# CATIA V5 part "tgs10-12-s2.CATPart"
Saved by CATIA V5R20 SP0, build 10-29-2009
Part number: TGS10-12-S2
Revision: 1
Definition: design
Nomenclature: TGS10-12-S2
Source: made
Description: NOT SPECIFIED
Bounding box of the stored display mesh (mm): x -22 to 0.8, y 0 to 10, z -4 to 4
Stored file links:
  C:\Users\Raffaele\Desktop\3D X SITO CF\I-MOLD\TGS-S2\tgs10-s2.step\tgs10-12-s2.CATPart
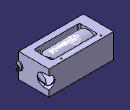
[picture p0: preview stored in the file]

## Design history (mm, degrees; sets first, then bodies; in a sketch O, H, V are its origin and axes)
Set1
  Line1 "LINE #4248": stored without definition
  DatumCurve1 "COMPOSITE_CURVE #4319"
  DatumCurve2 "COMPOSITE_CURVE #4370"
  DatumCurve3 "COMPOSITE_CURVE #4449"
  DatumCurve4 "COMPOSITE_CURVE #4492"
  DatumCurve5 "COMPOSITE_CURVE #4721"
  DatumCurve6 "COMPOSITE_CURVE #4863"
  DatumCurve7 "COMPOSITE_CURVE #4890"
  DatumCurve8 "COMPOSITE_CURVE #4948"
  DatumCurve9 "COMPOSITE_CURVE #5005"
  DatumCurve10 "COMPOSITE_CURVE #5034"
  DatumSurface1 "OPEN_SHELL #4238"
Body1 "MANIFOLD_SOLID_BREP #4239" (main body)
  Solid1: solid without history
